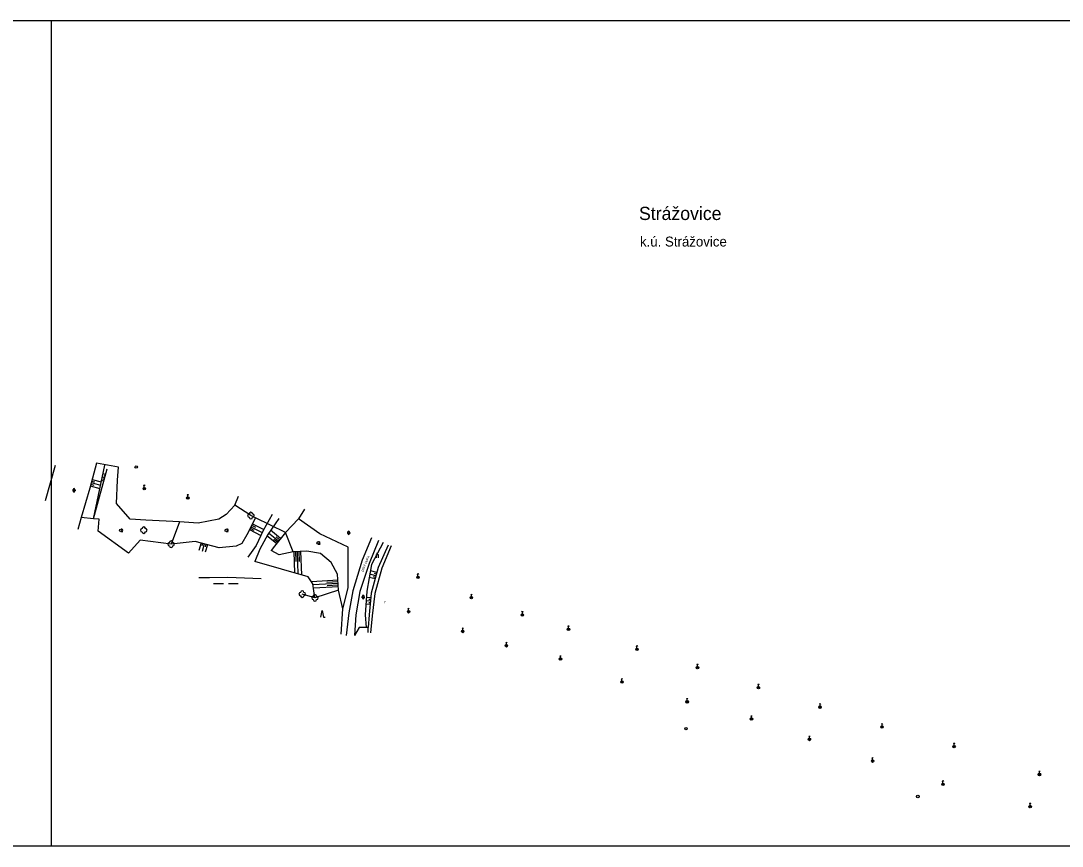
# Model space of a CAD drawing. Extents: x -582188 to -561562, y -1187250 to -1183500.
# Drawn here: x -569384.2 to -569068.9, y -1185000 to -1184750 of the extents above; entities that cross this region are included whole.
import ezdxf

# ---------------------------------------------------------------- set-up
doc = ezdxf.new("R2010")
doc.units = 0
for name, color, linetype in [('MAP_ZN_BP', 7, 'Continuous'), ('NÁZEV_K_Ú', 7, 'Continuous'), ('NÁZVY_SÍDEL_JEDNOTKY', 7, 'Continuous'), ('POMOC_POPIS', 7, 'Continuous'), ('ROZHRANÍ_PLOCH', 7, 'Continuous'), ('RÁMY_ML', 7, 'Continuous'), ('VÝŠKOPIS', 7, 'Continuous'), ('ZELEŇ', 7, 'Continuous'), ('ZN_BP', 7, 'Continuous'), ('ZN_DOPLŇKOVÉ', 7, 'Continuous'), ('ZN_KULTUR', 7, 'Continuous')]:
    doc.layers.add(name, color=color, linetype=linetype)

msp = doc.modelspace()

# ---------------------------------------------------------------- linework, layer by layer
at = {"layer": 'MAP_ZN_BP'}
for centre, radius in [((-569349.24, -1184885.12), 0.375), ((-569349.24, -1184885.12), 0.0005), ((-569182.82, -1184964.431), 0.375), ((-569182.82, -1184964.431), 0.0005), ((-569112.64, -1184984.941), 0.375), ((-569112.64, -1184984.941), 0.0005)]:
    msp.add_circle(centre, radius, dxfattribs=at)
at = {"layer": 'ROZHRANÍ_PLOCH'}
for points in [[(-569277.99, -1184906.63), (-569280.8, -1184913.35), (-569283.67, -1184922.62), (-569284.87, -1184929.3), (-569285.66, -1184936.16)], [(-569275.91, -1184907.4), (-569278.71, -1184914.36), (-569281.59, -1184922.82), (-569282.79, -1184929.92), (-569283.17, -1184936.16)], [(-569311.43, -1184919.02), (-569321.51, -1184918.63), (-569327.09, -1184918.67), (-569330.26, -1184918.69)]]:
    msp.add_lwpolyline(points, dxfattribs=at)
at = {"layer": 'RÁMY_ML'}
msp.add_line((-569375, -1184750), (-569375, -1185000), dxfattribs=at)
for points in [[(-568750, -1184750), (-569062.5, -1184750), (-569375, -1184750), (-569687.5, -1184750), (-570000, -1184750), (-570937.5, -1184750)], [(-568125, -1185000), (-568437.5, -1185000), (-569375, -1185000), (-569687.5, -1185000), (-570000, -1185000), (-570312.5, -1185000), (-570625, -1185000)]]:
    msp.add_lwpolyline(points, dxfattribs=at)
at = {"layer": 'VÝŠKOPIS'}
for p, q in [((-569358.53, -1184887.46), (-569359.31, -1184887.25)), ((-569363.01, -1184890.36), (-569362.05, -1184890.61)), ((-569362.88, -1184889.87), (-569360.01, -1184890.64)), ((-569362.75, -1184889.39), (-569361.79, -1184889.65)), ((-569362.62, -1184888.91), (-569359.81, -1184889.66)), ((-569359.05, -1184889.39), (-569359.71, -1184889.21)), ((-569358.79, -1184888.42), (-569359.51, -1184888.23)), ((-569358.92, -1184888.91), (-569359.22, -1184888.83)), ((-569358.66, -1184887.94), (-569358.96, -1184887.86)), ((-569363.14, -1184890.84), (-569360.26, -1184891.61)), ((-569314.31, -1184902.78), (-569313.15, -1184903.37)), ((-569314.08, -1184902.34), (-569310.66, -1184904.09)), ((-569314.99, -1184904.12), (-569311.52, -1184905.89)), ((-569314.76, -1184903.67), (-569313.61, -1184904.26)), ((-569314.54, -1184903.23), (-569311.1, -1184904.99)), ((-569306.79, -1184908.35), (-569309.67, -1184906.03)), ((-569306.16, -1184907.58), (-569309.15, -1184905.16)), ((-569305.53, -1184906.8), (-569308.58, -1184904.33)), ((-569329.63, -1184908.16), (-569330.26, -1184910.46)), ((-569329.14, -1184908.3), (-569329.35, -1184909.06)), ((-569328.66, -1184908.43), (-569329.29, -1184910.72)), ((-569328.18, -1184908.56), (-569328.39, -1184909.33)), ((-569327.7, -1184908.69), (-569328.33, -1184910.99)), ((-569306.47, -1184907.96), (-569307.55, -1184907.09)), ((-569305.84, -1184907.19), (-569306.92, -1184906.32)), ((-569301.54, -1184910.79), (-569301.29, -1184917.26)), ((-569301.04, -1184910.77), (-569300.92, -1184913.77)), ((-569300.54, -1184910.75), (-569300.28, -1184917.56)), ((-569300.04, -1184910.73), (-569299.92, -1184913.73)), ((-569299.54, -1184910.71), (-569299.26, -1184917.85)), ((-569276.95, -1184919.06), (-569278.69, -1184918.58)), ((-569276.68, -1184918.1), (-569278.49, -1184917.6)), ((-569276.41, -1184917.14), (-569278.34, -1184916.6)), ((-569276.81, -1184918.58), (-569277.42, -1184918.41)), ((-569276.55, -1184917.62), (-569277.15, -1184917.45)), ((-569288.16, -1184919.44), (-569296.21, -1184919.91)), ((-569288.11, -1184920.44), (-569295.73, -1184920.88)), ((-569288.05, -1184921.44), (-569295.57, -1184921.87)), ((-569288.14, -1184919.94), (-569291.51, -1184920.14)), ((-569288.08, -1184920.94), (-569291.46, -1184921.13)), ((-569278.28, -1184924.82), (-569279.55, -1184924.71)), ((-569278.45, -1184926.81), (-569279.69, -1184926.7)), ((-569278.36, -1184925.82), (-569279.62, -1184925.71)), ((-569278.41, -1184926.31), (-569278.87, -1184926.27)), ((-569278.32, -1184925.32), (-569278.79, -1184925.28))]:
    msp.add_line(p, q, dxfattribs=at)
for points in [[(-569362.13, -1184900.86), (-569358.75, -1184884.56)], [(-569308.1, -1184899.58), (-569310.8, -1184904.34), (-569312.91, -1184908.97), (-569315.41, -1184912.45)], [(-569313.18, -1184900.58), (-569315.78, -1184905.65), (-569317.31, -1184908.31), (-569319.01, -1184909.09), (-569324.14, -1184909.67), (-569331.35, -1184907.69), (-569338.69, -1184908.53)], [(-569306.12, -1184900.72), (-569309.41, -1184905.55), (-569311.87, -1184910.05), (-569313.32, -1184913.74)], [(-569304.08, -1184905), (-569307.43, -1184909.15), (-569308.41, -1184910.4)], [(-569274.5, -1184907.99), (-569278.01, -1184914.69), (-569279.42, -1184922.79), (-569279.92, -1184929.93), (-569279.67, -1184933.76)], [(-569272.93, -1184908.85), (-569275.98, -1184915.58), (-569278.15, -1184923.39), (-569278.72, -1184929.88), (-569279.03, -1184933.75)], [(-569287.99, -1184922.47), (-569288.27, -1184917.61), (-569290.25, -1184914.11), (-569293.47, -1184911.39), (-569297.61, -1184910.64), (-569301.77, -1184910.8), (-569305.97, -1184911.79), (-569308.41, -1184910.4)], [(-569295.13, -1184924.79), (-569295.78, -1184920.52), (-569297.23, -1184918.45), (-569313.32, -1184913.74)]]:
    msp.add_lwpolyline(points, dxfattribs=at)
at = {"layer": 'ZELEŇ'}
for points in [[(-569351.11, -1184900.91), (-569355.17, -1184896.25), (-569354.87, -1184889.12), (-569354.59, -1184885.21), (-569361.3, -1184883.97), (-569363.32, -1184891.52), (-569365.95, -1184900.49)], [(-569373.75, -1184884.69), (-569376.77, -1184895.36)], [(-569351.58, -1184911.2), (-569360.75, -1184904.56), (-569360.41, -1184900.95), (-569362.13, -1184900.86), (-569358.07, -1184885.73)], [(-569319.37, -1184896.68), (-569322.01, -1184899.54), (-569324.26, -1184900.93), (-569330.46, -1184902.19), (-569336.18, -1184901.77), (-569338.69, -1184908.53)], [(-569298.29, -1184897.93), (-569300.15, -1184900.88), (-569304.08, -1184905), (-569313.18, -1184900.58), (-569314.53, -1184899.85), (-569319.37, -1184896.68), (-569318.24, -1184894.03)], [(-569362.13, -1184900.86), (-569365.95, -1184900.49), (-569366.95, -1184904.09)], [(-569336.18, -1184901.77), (-569346.34, -1184901.26), (-569351.11, -1184900.91)], [(-569286.72, -1184928.11), (-569285.12, -1184921.79), (-569285.13, -1184909.44), (-569293.7, -1184905.39), (-569300.15, -1184900.88)], [(-569301.77, -1184910.8), (-569304.08, -1184905)], [(-569338.69, -1184908.53), (-569348.03, -1184907.3), (-569351.58, -1184911.2)], [(-569272.1, -1184909.03), (-569274.89, -1184915.84), (-569277, -1184923.47), (-569277.82, -1184930.2), (-569278.28, -1184935.36)], [(-569287.19, -1184935.78), (-569286.72, -1184928.11), (-569287.99, -1184922.47), (-569295.13, -1184924.79), (-569298.97, -1184923.65)], [(-569279.07, -1184935.25), (-569279.03, -1184933.75), (-569279.67, -1184933.76), (-569281.72, -1184933.77), (-569283.17, -1184936.16)]]:
    msp.add_lwpolyline(points, dxfattribs=at)
for centre in [(-569314.53, -1184899.85), (-569346.95, -1184904.28), (-569338.69, -1184908.53), (-569298.97, -1184923.65), (-569295.13, -1184924.79)]:
    msp.add_circle(centre, 0.0005, dxfattribs=at)
for centre, start, end in [((-569315.03, -1184899.85), 89.99999, 269.99999), ((-569314.53, -1184899.35), 0, 179.99999), ((-569314.03, -1184899.85), 270, 89.99999), ((-569314.53, -1184900.35), 179.99999, 359.99999), ((-569347.45, -1184904.28), 89.99999, 269.99999), ((-569346.95, -1184903.78), 0, 179.99999), ((-569346.95, -1184904.78), 179.99999, 359.99999), ((-569346.45, -1184904.28), 270, 89.99999), ((-569339.19, -1184908.53), 89.99999, 269.99999), ((-569338.69, -1184908.03), 0, 179.99999), ((-569338.69, -1184909.03), 179.99999, 359.99999), ((-569338.19, -1184908.53), 270, 89.99999), ((-569299.47, -1184923.65), 89.99999, 269.99999), ((-569298.97, -1184923.15), 0, 179.99999), ((-569298.97, -1184924.15), 179.99999, 359.99999), ((-569298.47, -1184923.65), 270, 89.99999), ((-569295.63, -1184924.79), 89.99999, 269.99999), ((-569295.13, -1184924.29), 0, 179.99999), ((-569294.63, -1184924.79), 270, 89.99999), ((-569295.13, -1184925.29), 179.99999, 359.99999)]:
    msp.add_arc(centre, 0.5, start, end, dxfattribs=at)
at = {"layer": 'ZN_BP'}
for p, q in [((-569347.065, -1184891.964), (-569346.536, -1184891.436)), ((-569346.536, -1184891.968), (-569347.065, -1184891.436)), ((-569346.8, -1184891.325), (-569346.8, -1184890.575)), ((-569333.61, -1184894.135), (-569333.61, -1184893.385)), ((-569333.875, -1184894.774), (-569333.346, -1184894.246)), ((-569333.346, -1184894.778), (-569333.875, -1184894.246)), ((-569264.225, -1184918.814), (-569263.696, -1184918.286)), ((-569263.696, -1184918.818), (-569264.225, -1184918.286)), ((-569263.96, -1184918.175), (-569263.96, -1184917.425)), ((-569248.045, -1184925.004), (-569247.516, -1184924.476)), ((-569247.516, -1184925.008), (-569248.045, -1184924.476)), ((-569247.78, -1184924.365), (-569247.78, -1184923.615)), ((-569266.79, -1184928.625), (-569266.79, -1184927.875)), ((-569267.055, -1184929.264), (-569266.526, -1184928.736)), ((-569266.526, -1184929.268), (-569267.055, -1184928.736)), ((-569232.625, -1184930.224), (-569232.096, -1184929.696)), ((-569232.096, -1184930.228), (-569232.625, -1184929.696)), ((-569232.36, -1184929.585), (-569232.36, -1184928.835)), ((-569250.42, -1184934.585), (-569250.42, -1184933.835)), ((-569218.665, -1184934.574), (-569218.136, -1184934.046)), ((-569218.136, -1184934.578), (-569218.665, -1184934.046)), ((-569218.4, -1184933.935), (-569218.4, -1184933.185)), ((-569250.685, -1184935.224), (-569250.156, -1184934.696)), ((-569250.156, -1184935.228), (-569250.685, -1184934.696)), ((-569237.465, -1184939.564), (-569236.936, -1184939.036)), ((-569236.936, -1184939.568), (-569237.465, -1184939.036)), ((-569237.2, -1184938.925), (-569237.2, -1184938.175)), ((-569197.935, -1184940.614), (-569197.406, -1184940.086)), ((-569197.406, -1184940.618), (-569197.935, -1184940.086)), ((-569197.67, -1184939.975), (-569197.67, -1184939.225)), ((-569221.075, -1184943.594), (-569220.546, -1184943.066)), ((-569220.546, -1184943.598), (-569221.075, -1184943.066)), ((-569220.81, -1184942.955), (-569220.81, -1184942.205)), ((-569179.605, -1184946.194), (-569179.076, -1184945.666)), ((-569179.076, -1184946.198), (-569179.605, -1184945.666)), ((-569179.34, -1184945.555), (-569179.34, -1184944.805)), ((-569202.475, -1184950.554), (-569201.946, -1184950.026)), ((-569201.946, -1184950.558), (-569202.475, -1184950.026)), ((-569202.21, -1184949.915), (-569202.21, -1184949.165)), ((-569161.155, -1184952.234), (-569160.626, -1184951.706)), ((-569160.626, -1184952.238), (-569161.155, -1184951.706)), ((-569160.89, -1184951.595), (-569160.89, -1184950.845)), ((-569182.735, -1184956.534), (-569182.206, -1184956.006)), ((-569182.206, -1184956.538), (-569182.735, -1184956.006)), ((-569182.715, -1184956.524), (-569182.186, -1184955.996)), ((-569182.186, -1184956.528), (-569182.715, -1184955.996)), ((-569182.47, -1184955.895), (-569182.47, -1184955.145)), ((-569182.45, -1184955.885), (-569182.45, -1184955.135)), ((-569142.505, -1184958.144), (-569141.976, -1184957.616)), ((-569141.976, -1184958.148), (-569142.505, -1184957.616)), ((-569142.24, -1184957.505), (-569142.24, -1184956.755)), ((-569163.255, -1184961.764), (-569162.726, -1184961.236)), ((-569162.726, -1184961.768), (-569163.255, -1184961.236)), ((-569162.99, -1184961.125), (-569162.99, -1184960.375)), ((-569123.47, -1184963.545), (-569123.47, -1184962.795)), ((-569123.735, -1184964.184), (-569123.206, -1184963.656)), ((-569123.206, -1184964.188), (-569123.735, -1184963.656)), ((-569145.715, -1184967.934), (-569145.186, -1184967.406)), ((-569145.186, -1184967.938), (-569145.715, -1184967.406)), ((-569145.45, -1184967.295), (-569145.45, -1184966.545)), ((-569101.66, -1184969.485), (-569101.66, -1184968.735)), ((-569101.925, -1184970.124), (-569101.396, -1184969.596)), ((-569101.396, -1184970.128), (-569101.925, -1184969.596)), ((-569126.595, -1184974.494), (-569126.066, -1184973.966)), ((-569126.066, -1184974.498), (-569126.595, -1184973.966)), ((-569126.33, -1184973.855), (-569126.33, -1184973.105)), ((-569076.095, -1184978.554), (-569075.566, -1184978.026)), ((-569075.566, -1184978.558), (-569076.095, -1184978.026)), ((-569075.83, -1184977.915), (-569075.83, -1184977.165)), ((-569105.305, -1184981.524), (-569104.776, -1184980.996)), ((-569104.776, -1184981.528), (-569105.305, -1184980.996)), ((-569105.04, -1184980.885), (-569105.04, -1184980.135)), ((-569078.895, -1184988.264), (-569078.366, -1184987.736)), ((-569078.366, -1184988.268), (-569078.895, -1184987.736)), ((-569078.63, -1184987.625), (-569078.63, -1184986.875))]:
    msp.add_line(p, q, dxfattribs=at)
for points in [[(-569346.925, -1184890.825), (-569346.8, -1184890.575), (-569346.675, -1184890.825)], [(-569333.735, -1184893.635), (-569333.61, -1184893.385), (-569333.485, -1184893.635)], [(-569264.085, -1184917.675), (-569263.96, -1184917.425), (-569263.835, -1184917.675)], [(-569247.905, -1184923.865), (-569247.78, -1184923.615), (-569247.655, -1184923.865)], [(-569266.915, -1184928.125), (-569266.79, -1184927.875), (-569266.665, -1184928.125)], [(-569232.485, -1184929.085), (-569232.36, -1184928.835), (-569232.235, -1184929.085)], [(-569250.545, -1184934.085), (-569250.42, -1184933.835), (-569250.295, -1184934.085)], [(-569218.525, -1184933.435), (-569218.4, -1184933.185), (-569218.275, -1184933.435)], [(-569237.325, -1184938.425), (-569237.2, -1184938.175), (-569237.075, -1184938.425)], [(-569197.795, -1184939.475), (-569197.67, -1184939.225), (-569197.545, -1184939.475)], [(-569220.935, -1184942.455), (-569220.81, -1184942.205), (-569220.685, -1184942.455)], [(-569179.465, -1184945.055), (-569179.34, -1184944.805), (-569179.215, -1184945.055)], [(-569202.335, -1184949.415), (-569202.21, -1184949.165), (-569202.085, -1184949.415)], [(-569161.015, -1184951.095), (-569160.89, -1184950.845), (-569160.765, -1184951.095)], [(-569182.595, -1184955.395), (-569182.47, -1184955.145), (-569182.345, -1184955.395)], [(-569182.575, -1184955.385), (-569182.45, -1184955.135), (-569182.325, -1184955.385)], [(-569142.365, -1184957.005), (-569142.24, -1184956.755), (-569142.115, -1184957.005)], [(-569163.115, -1184960.625), (-569162.99, -1184960.375), (-569162.865, -1184960.625)], [(-569123.595, -1184963.045), (-569123.47, -1184962.795), (-569123.345, -1184963.045)], [(-569145.575, -1184966.795), (-569145.45, -1184966.545), (-569145.325, -1184966.795)], [(-569101.785, -1184968.985), (-569101.66, -1184968.735), (-569101.535, -1184968.985)], [(-569126.455, -1184973.355), (-569126.33, -1184973.105), (-569126.205, -1184973.355)], [(-569075.955, -1184977.415), (-569075.83, -1184977.165), (-569075.705, -1184977.415)], [(-569105.165, -1184980.385), (-569105.04, -1184980.135), (-569104.915, -1184980.385)], [(-569078.755, -1184987.125), (-569078.63, -1184986.875), (-569078.505, -1184987.125)]]:
    msp.add_lwpolyline(points, dxfattribs=at)
for centre in [(-569346.8, -1184891.7), (-569333.61, -1184894.51), (-569263.96, -1184918.55), (-569247.78, -1184924.74), (-569266.79, -1184929), (-569232.36, -1184929.96), (-569250.42, -1184934.96), (-569218.4, -1184934.31), (-569237.2, -1184939.3), (-569197.67, -1184940.35), (-569220.81, -1184943.33), (-569179.34, -1184945.93), (-569202.21, -1184950.29), (-569160.89, -1184951.97), (-569182.47, -1184956.27), (-569182.45, -1184956.26), (-569142.24, -1184957.88), (-569162.99, -1184961.5), (-569123.47, -1184963.92), (-569145.45, -1184967.67), (-569101.66, -1184969.86), (-569126.33, -1184974.23), (-569075.83, -1184978.29), (-569105.04, -1184981.26), (-569078.63, -1184988)]:
    msp.add_circle(centre, 0.375, dxfattribs=at)
at = {"layer": 'ZN_DOPLŇKOVÉ'}
msp.add_line((-569276.27, -1184911.63), (-569276.27, -1184911.13), dxfattribs=at)
msp.add_lwpolyline([(-569276.52, -1184912.63), (-569276.52, -1184911.63), (-569276.02, -1184911.63), (-569276.02, -1184912.63)], dxfattribs=at)
at = {"layer": 'ZN_KULTUR'}
for p, q in [((-569368.56, -1184892.2), (-569367.56, -1184892.2)), ((-569368.31, -1184892.45), (-569368.31, -1184891.95)), ((-569367.81, -1184892.45), (-569367.81, -1184891.95)), ((-569353.94, -1184904.685), (-569353.315, -1184904.685)), ((-569322, -1184904.685), (-569321.375, -1184904.685)), ((-569285.41, -1184905.06), (-569284.41, -1184905.06)), ((-569285.16, -1184905.31), (-569285.16, -1184904.81)), ((-569284.66, -1184905.31), (-569284.66, -1184904.81)), ((-569294.21, -1184908.505), (-569293.585, -1184908.505)), ((-569325.84, -1184920.48), (-569322.84, -1184920.48)), ((-569321.34, -1184920.48), (-569318.34, -1184920.48)), ((-569281.02, -1184924.54), (-569280.02, -1184924.54)), ((-569280.77, -1184924.79), (-569280.77, -1184924.29)), ((-569280.27, -1184924.79), (-569280.27, -1184924.29))]:
    msp.add_line(p, q, dxfattribs=at)
msp.add_lwpolyline([(-569293.315, -1184930.59), (-569292.94, -1184928.59), (-569292.565, -1184930.59), (-569292.065, -1184930.59)], dxfattribs=at)
for centre in [(-569353.94, -1184904.31), (-569322, -1184904.31), (-569294.21, -1184908.13)]:
    msp.add_circle(centre, 0.375, dxfattribs=at)
for centre, radius, start, end in [((-569368.06, -1184891.95), 0.25, 0, 179.99999), ((-569368.06, -1184892.45), 0.25, 179.99999, 359.99999), ((-569353.69, -1184904.31), 0.375, 249.49437, 109.04743), ((-569321.75, -1184904.31), 0.375, 249.49437, 109.04743), ((-569284.91, -1184904.81), 0.25, 0, 179.99999), ((-569284.91, -1184905.31), 0.25, 179.99999, 359.99999), ((-569293.96, -1184908.13), 0.375, 249.49437, 109.04743), ((-569280.52, -1184924.29), 0.25, 0, 179.99999), ((-569280.52, -1184924.79), 0.25, 179.99999, 359.99999)]:
    msp.add_arc(centre, radius, start, end, dxfattribs=at)

# ---------------------------------------------------------------- texts
at = {"layer": 'NÁZEV_K_Ú'}
msp.add_text('k.ú. Strážovice', height=3, dxfattribs=at).set_placement((-569196.76, -1184818.36))
at = {"layer": 'NÁZVY_SÍDEL_JEDNOTKY'}
msp.add_text('Strážovice', height=4, dxfattribs=at).set_placement((-569197.04, -1184810.34))
at = {"layer": 'POMOC_POPIS'}
msp.add_text('polní cesta', height=0.75, rotation=68.08513, dxfattribs=at).set_placement((-569280.54, -1184916.91))
at = {"layer": 'ZN_KULTUR'}
msp.add_text('r', height=1, dxfattribs=at).set_placement((-569274.108, -1184926.462))

doc.saveas('drawing.dxf')
